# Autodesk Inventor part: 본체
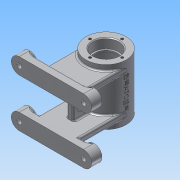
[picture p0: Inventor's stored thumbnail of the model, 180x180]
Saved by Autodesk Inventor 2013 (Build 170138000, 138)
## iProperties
Created: 2015-11
Part Number: 본체
Material: 알루미늄 6061
Document SubType Name: Modeling
Designer: Administrator
Density: 2.71 g/cm^3
Mass: 359.098 g
Surface Area: 459.586 cm^2
Volume: 132.509 cm^3
Author: Administrator
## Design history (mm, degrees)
sketch "스케치1"
  geometry: C1 r 25 at (0, 0); 1 further point
  constraints: 1 centre point, 1 coincident
  dimensions: "d0" = 50 diameter of C1
extrude "돌출1" new body sketch "스케치1" distance "d1" = 35; taper "d2" = 0 deg
hole "구멍1" diameter "d5" = 28; stored, may be unused: countersink angle "d9" = 90 deg, drill point angle "d11" = 0 deg; dims "d3" = 10, "d4" = 10, "d6" = 6, "d7" = 32, "d8" = 12, "d10" = 14
sketch "스케치2"
  geometry: C1 r 25 at (0, 0) reference; C2 r 21 at (0, 0)
  constraints: 1 centre point, 1 coincident
  dimensions: "d12" = 42 diameter of C2
extrude "돌출2" cut sketch "스케치2" distance "d13" = 21; taper "d14" = 0 deg
sketch "스케치3"
  geometry: C1 r 16 at (0, 0) reference; 1 further point
  constraints: 1 vertical alignment
  dimensions: "d15" = 20 distance of C1.centre point (0, 20)
hole "구멍2" sketch "스케치3" at (0, 20) diameter "d16" = 3.242; stored, may be unused: countersink angle "d20" = 90 deg, drill point angle "d22" = 118 deg; dims "d17" = 8, "d18" = 32, "d19" = 12, "d21" = 10
chamfer "모따기1" distance "d26" = 1; stored, may be unused: second distance "d27" = 2, angle "d28" = 45 deg
fillet "모깎기1" dims "d29" = 0.3
node "작업 평면1"
sketch "스케치4"
  geometry: C1 r 5 at (0, 0); 1 further point
  constraints: 1 centre point, 1 coincident
  dimensions: "d31" = 10 diameter of C1
extrude "돌출3" join sketch "스케치4" stored distance "d32" = 11; taper "d33" = 0 deg
hole "구멍3" diameter "d36" = 5.188; stored, may be unused: countersink angle "d40" = 90 deg, drill point angle "d42" = 118 deg; dims "d34" = 10, "d35" = 10, "d37" = 8, "d38" = 32, "d39" = 12, "d41" = 10
sketch "스케치5"
  geometry: L1 (0, 0)-(-14, -24.249); L2 (0, 0)-(28, 0)
  constraints: 4 end point, 1 equal length, 1 horizontal
  dimensions: "d43" = 28 distance of L1.start L1.end; "d44" = 120 deg angle of L1 L2
node "작업 평면2"
sketch "스케치6"
  geometry: C1 r 6 at (0, 0); 1 further point
  constraints: 1 centre point, 1 coincident
  dimensions: "d45" = 12 diameter of C1
extrude "돌출4" join sketch "스케치6" stored distance "d46" = 11; taper "d47" = 0 deg
sketch "스케치7"
  geometry: C1 r 6 at (0, 0) reference; 1 further point
  constraints: 1 coincident
node "작업 평면3"
node "작업 평면4"
sketch "스케치13"
  geometry: L1 (-40, -20)-(40, -20); L2 (40, -20)-(40, -40); L3 (40, -40)-(-40, -40); L4 (-40, -40)-(-40, -20); 4 further points
  constraints: 8 end point, 3 midpoint, 3 vertical alignment, 2 parallel, 1 horizontal, 1 perpendicular, 4 other
  dimensions: "d114" = 80 distance of L2.end L3.end; "d116" = 20 distance of L3.end L1.start; "d117" = 40 distance from line of L3 point (0, 0)
extrude "돌출8" join sketch "스케치13" distance "d118" = 10; taper "d119" = 0 deg
extrude "돌출9" join sketch "스케치13" distance "d120" = 13; taper "d121" = 0 deg
sketch "스케치14"
  geometry: L1 (-40, 20)-(40, 20) reference; L2 (-25, 28)-(25, 28); L3 (25, 28)-(25, 20); L4 (25, 20)-(-25, 20); L5 (-25, 20)-(-25, 28); 2 further points
  constraints: 8 end point, 2 midpoint, 2 parallel, 1 horizontal, 1 perpendicular
  dimensions: "d122" = 8 distance of L4.end L2.start; "d124" = 50 distance of L2.start L2.end
extrude "돌출10" join sketch "스케치14" stored distance "d125" = 13; taper "d126" = 0 deg
hole "구멍7" diameter "d129" = 6; stored, may be unused: countersink angle "d133" = 90 deg, drill point angle "d135" = 0 deg; dims "d127" = 10, "d128" = 10, "d130" = 8, "d131" = 12, "d132" = 4, "d134" = 10
hole "구멍8" diameter "d138" = 6; stored, may be unused: countersink angle "d142" = 90 deg, drill point angle "d144" = 0 deg; dims "d136" = 10, "d137" = 10, "d139" = 8, "d140" = 12, "d141" = 4, "d143" = 10
fillet "모깎기12" dims "d145" = 2
fillet "모깎기13" dims "d146" = 2
fillet "모깎기14" dims "d147" = 2
sketch "스케치15"
  geometry: L1 (-45, 20)-(-45, -20); L2 (25, -5)-(25, -35) reference; L3 (25, -35)-(21.621, -35) reference; L4 (21.621, -35)-(21.621, -25) reference; L5 (21.621, -25)-(20, -24.026) reference; L6 (20, -24.026)-(18.379, -25) reference; L7 (18.379, -25)-(18.379, -35) reference; L8 (18.379, -35)-(17, -35) reference; L9 (17, -35)-(16, -34) reference; L10 (16, -34)-(16, -23.3) reference; L11 (15.7, -23)-(14, -23) reference; L12 (14, -23)-(14, -21) reference; L13 (14, -21)-(21, -21) reference; L14 (21, -21)-(21, -2.594) reference; L15 (21, -2.594)-(28, -2.594) reference; L16 (28, -2.594)-(28, -5) reference; L17 (28, -5)-(25, -5) reference; L18 (-21.621, 25)-(-20, 24.026) reference; L19 (-20, 24.026)-(-18.379, 25) reference; L20 (-18.379, 25)-(-18.379, 35) reference; L21 (-18.379, 35)-(-17, 35) reference; L22 (-17, 35)-(-16, 34) reference; L23 (-16, 34)-(-16, 23.3) reference; L24 (-15.7, 23)-(-14, 23) reference; L25 (-14, 23)-(-14, 21) reference; L26 (-14, 21)-(-21, 21) reference; L27 (-21, 21)-(-21, -21) reference; L28 (-21, -21)-(-14, -21) reference; L29 (-14, -21)-(-14, -23) reference; L30 (-14, -23)-(-15.7, -23) reference; L31 (-16, -23.3)-(-16, -34) reference; L32 (-16, -34)-(-17, -35) reference; L33 (-17, -35)-(-18.379, -35) reference; L34 (-18.379, -35)-(-18.379, -25) reference; L35 (-18.379, -25)-(-20, -24.026) reference; L36 (-20, -24.026)-(-21.621, -25) reference; L37 (-21.621, -25)-(-21.621, -35) reference; L38 (-21.621, -35)-(-25, -35) reference; L39 (-25, -35)-(-25, -28) reference; L40 (-25, -28)-(-56, -28) reference; L41 (-58, -30)-(-58, -38) reference; L42 (-60, -40)-(-68, -40) reference; L43 (-68, -40)-(-68, -20) reference; L44 (-68, -20)-(-25, -20) reference; L45 (-25, -20)-(-25, 20) reference; L46 (-25, 20)-(-68, 20) reference; L47 (-68, 20)-(-68, 40) reference; L48 (-68, 40)-(-60, 40) reference; L49 (-58, 38)-(-58, 30) reference; L50 (-56, 28)-(-25, 28) reference; L51 (-25, 28)-(-25, 35) reference; L52 (-25, 35)-(-21.621, 35) reference; L53 (-21.621, 35)-(-21.621, 25) reference; L54 (20, 24.026)-(21.621, 25) reference; L55 (21.621, 25)-(21.621, 35) reference; L56 (21.621, 35)-(25, 35) reference; L57 (25, 35)-(25, 5) reference; L58 (25, 5)-(28, 5) reference; L59 (28, 5)-(28, 2.594) reference; L60 (28, 2.594)-(21, 2.594) reference; L61 (21, 2.594)-(21, 21) reference; L62 (21, 21)-(14, 21) reference; L63 (14, 21)-(14, 23) reference; L64 (14, 23)-(15.7, 23) reference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; A1 r 0.3 centre (15.7, -23.3) between (16, -23.3) and (15.7, -23) reference; A2 r 0.3 centre (-15.7, 23.3) between (-16, 23.3) and (-15.7, 23) reference; A3 r 0.3 centre (-15.7, -23.3) between (-15.7, -23) and (-16, -23.3) reference; A4 r 2 centre (-56, -30) between (-56, -28) and (-58, -30) reference; A5 r 2 centre (-60, -38) between (-60, -40) and (-58, -38) reference; A6 r 2 centre (-60, 38) between (-58, 38) and (-60, 40) reference; A7 r 2 centre (-56, 30) between (-58, 30) and (-56, 28) reference; A8 r 0.3 centre (15.7, 23.3) between (15.7, 23) and (16, 23.3) reference; 1 further point
  constraints: 2 end point, 2 point on line, 1 vertical
  dimensions: "d148" = 20 distance between parallel lines of L1 L45
feature "리브2" sketch "스케치15" dims "d149" = 1, "d150" = 8, "d151" = 0, "d152" = 0, "d153" = 1, "d154" = 1
sketch "스케치17" dims "d158" = 23
  geometry: L1 (40, 0)-(0, 0) reference; L2 (12, 13.5)-(28, 13.5); L3 (28, 13.5)-(28, 6.5); L4 (28, 6.5)-(12, 6.5); L5 (12, 6.5)-(12, 13.5); L6 (-7, -23)-(-13, -23) reference; 5 further points
  constraints: 8 end point, 4 midpoint, 3 vertical alignment, 2 parallel, 1 horizontal, 1 perpendicular, 4 other
  dimensions: "d155" = 7 distance of L4.end L2.start; "d157" = 33 distance from line of L6 point (12, 10)
extrude "돌출11" cut sketch "스케치17" stored distance "d159" = 13; taper "d160" = 0 deg
fillet "모깎기15" dims "d161" = 2
fillet "모깎기16" dims "d162" = 2
fillet "모깎기17" dims "d163" = 2
hole "구멍9" diameter "d166" = 5.188; stored, may be unused: countersink angle "d170" = 90 deg, drill point angle "d172" = 118 deg; dims "d164" = 10, "d165" = 10, "d167" = 8, "d168" = 12, "d169" = 4, "d171" = 10
fillet "모깎기18" dims "d173" = 3
node "작업 평면5"
sketch "스케치18"
  geometry: 2 further points
  constraints: 1 coincident, 1 other
feature "엠보싱1" sketch "스케치18" dims "d174" = 0.5, "d175" = 0
fillet "모깎기19" dims "d176" = 0.3
chamfer "모따기3" distance "d177" = 1; stored, may be unused: second distance "d178" = 2, angle "d179" = 45 deg
fillet "모깎기20" dims "d180" = 2
node "솔리드1"
pattern_circular "원형 패턴1" dims angle "d24" = 360 deg
mirror "대칭1"
mirror "대칭3"
node "절단 모서리 투영2"
other parameters: "d30" = 28, "d48" = -62, "d113" = -68
